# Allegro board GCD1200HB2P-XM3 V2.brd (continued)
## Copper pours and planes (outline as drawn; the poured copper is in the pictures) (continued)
N5778706 on BOTTOM: 33.62,20.7 33.69,20.88 33.87,20.96 38.95,20.96 39.13,20.88 39.2,20.7 39.2,18.8 39.13,18.62 38.95,18.54 33.87,18.54 33.69,18.62 33.62,18.8
N5778794 on TOP: 38.3,25.78 38.13,25.7 38.05,25.52 38.05,22.51 38.1,22.28 38.23,22.08 39.17,21.14 39.31,20.94 39.35,20.7 39.35,18.57 39.28,18.39 39.1,18.31 36.15,18.31 35.97,18.24 35.9,18.06 35.9,16.03 35.97,15.85 36.15,15.77 40.12,15.77 40.3,15.85 40.37,16.03 40.37,25.52 40.3,25.7 40.12,25.78
N5778794 on BOTTOM: 33.62,18.03 33.69,18.21 33.87,18.29 38.95,18.29 39.13,18.21 39.2,18.03 39.2,16.13 39.13,15.95 38.95,15.88 33.87,15.88 33.69,15.95 33.62,16.13
N5780153 on TOP: 30.32,32.96 30.39,33.14 30.57,33.21 33.74,33.21 33.92,33.14 33.99,32.96 33.99,29.8 33.95,29.57 33.81,29.37 33.16,28.72 33.03,28.52 32.98,28.29 32.98,26.39 32.91,26.21 32.73,26.14 30.57,26.14 30.39,26.21 30.32,26.39
N5927082 on BOTTOM: 36.85,41.93 36.92,42.11 37.1,42.19 38.78,42.19 38.96,42.11 39.03,41.93 39.03,38 38.96,37.82 38.78,37.74 37.1,37.74 36.92,37.82 36.85,38
N5961728 on TOP: 50.44,18.66 50.62,18.59 50.69,18.41 50.69,11.47 50.62,11.29 50.44,11.22 49.74,11.22 49.56,11.29 49.49,11.47 49.49,18.41 49.56,18.59 49.74,18.66
N6009836 on BOTTOM: 4.78,42.54 4.78,37.33 1.48,37.33 1.48,42.54
N6026743 on TOP: 52.11,65.78 52.56,65.6 52.75,65.15 52.75,62.1 52.56,61.65 52.11,61.46 46.39,61.46 45.94,61.65 45.75,62.1 45.75,65.15 45.94,65.6 46.39,65.78
N6026743 on BOTTOM: 52.11,65.02 52.56,64.83 52.75,64.38 52.75,61.72 52.56,61.27 52.11,61.08 46.39,61.08 45.94,61.27 45.75,61.72 45.75,64.38 45.94,64.83 46.39,65.02
N6026743 on LAYER2, LAYER3, LAYER4, LAYER5: 52.11,65.78 52.56,65.6 52.75,65.15 52.75,61.72 52.56,61.27 52.11,61.08 46.39,61.08 45.94,61.27 45.75,61.72 45.75,65.15 45.94,65.6 46.39,65.78

Small or netless copper shapes (teardrops, artwork), in the pictures only: 4 on TOP, 5 on BOTTOM, 1 on LAYER2, 2 on LAYER3, 2 on LAYER4, 3 on LAYER5

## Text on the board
Ref Des/Silkscreen Bottom: XM3 | Gate Driver | Version 0.2
Ref Des/Silkscreen Top: G | R | HS-GS | LS-GS | S | HS-OC | NTC | ON | OFF
COMPVAL_TYPE_TOP: FIGURE | FINISHED_SIZE | 13.0 | 40.0 | 175.0 | DRILL CHART: TOP to BOTTOM | ALL UNITS ARE IN MILS | PLATED | NON-PLATED | QTY | 430 | 26 | 4 | 460 | TOTAL HOLES:
